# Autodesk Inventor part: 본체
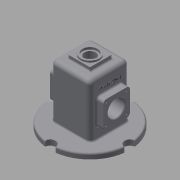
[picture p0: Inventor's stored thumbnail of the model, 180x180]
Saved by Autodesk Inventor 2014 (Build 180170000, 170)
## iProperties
Created: 2018-07
Part Number: 본체
Material: Generic
Document SubType Name: Modeling
Designer: kh
Density: 1 g/cm^3
Appearance: Default
Author: kh
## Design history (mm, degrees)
sketch "Sketch1"
  geometry: C1 r 75 at (0, 0); 1 further point
  constraints: 1 centre point, 1 coincident
  dimensions: "d0" = 150 diameter of C1
extrude "Extrusion1" new body sketch "Sketch1" distance "d1" = 10; taper "d2" = 0 deg
sketch "Sketch2"
  geometry: L1 (-37, -37)-(37, -37); L2 (37, -37)-(37, 37); L3 (37, 37)-(-37, 37); L4 (-37, 37)-(-37, -37); L5 (-37, -37)-(37, 37); L6 (37, -37)-(-37, 37); 1 further point
  constraints: 12 end point, 2 midpoint, 2 parallel, 1 horizontal, 1 perpendicular
  dimensions: "d3" = 74 distance of L2.end L3.end; "d4" = 74 distance of L1.end L2.end
extrude "Extrusion2" join sketch "Sketch2" distance "d5" = 100; taper "d6" = 0 deg
sketch "Sketch3"
  geometry: L1 (0, 74)-(0, 0) reference; L2 (0, 74)-(-100, 74) reference; L3 (-100, 0)-(-100, 74) reference; L4 (0, 0)-(-100, 0) reference; L5 (-20, 12)-(-70, 12); L6 (-70, 12)-(-70, 62); L7 (-70, 62)-(-20, 62); L8 (-20, 62)-(-20, 12); L9 (-20, 12)-(-70, 62); L10 (-70, 12)-(-20, 62); L11 (10, -38)-(10, 112) reference; L12 (10, 37)-(-46.721, 37); 2 further points
  constraints: 14 end point, 3 midpoint, 2 parallel, 2 perpendicular, 1 horizontal, 1 point on line
  dimensions: "d7" = 50 distance of L5.end L6.end; "d8" = 50 distance of L5.start L5.end; "d9" = 55 distance from line of L11 point (-45, 37)
extrude "Extrusion3" join sketch "Sketch3" distance "d10" = 13; taper "d11" = 0 deg
mirror "Mirror1"
sketch "Sketch4"
  geometry: L1 (0, 0)-(0, 109.307); L2 (0, 105)-(-32, 105); L3 (-37, 80)-(-50, 80) reference; L4 (-37, 10)-(-37, 110) reference; L5 (-75, 0)-(75, 0) reference; L6 (-32, 105)-(-32, 80); L7 (-32, 80)-(-25, 77.452); L8 (-25, 77.452)-(-25, 32.548); L9 (-37, 30)-(-50, 30) reference; L10 (-25, 32.548)-(-32, 30); L11 (-32, 30)-(-32, 0); L12 (-37, 110)-(37, 110) reference; L13 (-25, 55)-(-41.925, 55); L14 (32, 30)-(32, 0); L15 (25, 32.548)-(32, 30); L16 (25, 77.452)-(25, 32.548); L17 (32, 80)-(25, 77.452); L18 (32, 105)-(32, 80); L19 (0, 105)-(32, 105); L20 (32, 0)-(-32, 0)
  constraints: 30 end point, 6 symmetric about line, 3 perpendicular, 3 point on line, 2 parallel, 1 collinear, 1 midpoint, 1 vertical, 1 other
  dimensions: "d13" = 5 distance between parallel lines of L2 L12; "d14" = 32 distance of L2.start L2.end; "d16" = 32 distance between parallel lines of L1 L11; "d17" = 7 distance between parallel lines of L8 L6; "d18" = 50 distance of L10.end L6.end; "d19" = 110 deg angle of L11 L10
extrude "Extrusion4" cut sketch "Sketch4" stored distance "d20" = 64; taper "d21" = 0 deg
sketch "Sketch5"
  geometry: L1 (-70, 12)-(-20, 12) reference; L2 (-20, 12)-(-20, 62) reference; L3 (-20, 62)-(-70, 62) reference; L4 (-70, 62)-(-70, 12) reference; L5 (-20, 12)-(-70, 62); C1 r 16 at (-45, 37); 1 further point
  constraints: 2 end point, 1 centre point, 1 midpoint
  dimensions: "d22" = 32 diameter of C1
extrude "Extrusion5" cut sketch "Sketch5" stored distance "d23" = 64; taper "d24" = 0 deg
sketch "Sketch6"
  geometry: L1 (-37, -37)-(37, -37) reference; L2 (37, -37)-(37, 37) reference; L3 (37, 37)-(-37, 37) reference; L4 (-37, 37)-(-37, -37) reference; L5 (-20, -20)-(20, -20); L6 (20, -20)-(20, 20); L7 (20, 20)-(-20, 20); L8 (-20, 20)-(-20, -20); L9 (-20, -20)-(20, 20); L10 (20, -20)-(-20, 20); 1 further point
  constraints: 12 end point, 2 midpoint, 2 parallel, 1 horizontal, 1 perpendicular
  dimensions: "d25" = 40 distance of L6.end L7.end; "d26" = 40 distance of L5.end L6.end
extrude "Extrusion6" join sketch "Sketch6" distance "d27" = 7; taper "d28" = 0 deg
sketch "Sketch7"
  geometry: C1 r 17.5 at (0, 0); 1 further point
  constraints: 1 centre point, 1 coincident
  dimensions: "d29" = 35 diameter of C1
extrude "Extrusion7" join sketch "Sketch7" distance "d30" = 3; taper "d31" = 0 deg
hole "Hole1" diameter "d34" = 21; stored, may be unused: countersink angle "d38" = 90 deg, drill point angle "d40" = 118 deg; dims "d32" = 10, "d33" = 10, "d35" = 6, "d36" = 28, "d37" = 4, "d39" = 8
fillet "Fillet1" dims "d41" = 8
fillet "Fillet2" dims "d42" = 6
fillet "Fillet3" dims "d43" = 3
fillet "Fillet4" dims "d44" = 3
fillet "Fillet5" dims "d45" = 3
fillet "Fillet6" dims "d46" = 3
chamfer "Chamfer1" distance "d47" = 1; stored, may be unused: second distance "d48" = 2, angle "d49" = 45 deg
sketch "Sketch8"
  geometry: L1 (-70, 56)-(-70, 18) reference; L2 (-64, 12)-(-26, 12) reference; L3 (-20, 18)-(-20, 56) reference; L4 (-26, 62)-(-64, 62) reference; C1 r 17 at (-45, 37) reference; A1 r 6 centre (-64, 56) between (-64, 62) and (-70, 56) reference; A2 r 6 centre (-64, 18) between (-70, 18) and (-64, 12) reference; A3 r 6 centre (-26, 18) between (-26, 12) and (-20, 18) reference; A4 r 6 centre (-26, 56) between (-20, 56) and (-26, 62) reference; 1 further point
hole "Hole2" sketch "Sketch8" at (-64, 56), (-64, 18), (-26, 18), (-26, 56) diameter "d50" = 3.242; stored, may be unused: countersink angle "d54" = 90 deg, drill point angle "d56" = 118 deg; dims "d51" = 8, "d52" = 28, "d53" = 4, "d55" = 10
mirror "Mirror2"
fillet "Fillet7" dims "d57" = 8
sketch "Sketch9"
  geometry: L1 (0, 66)-(-89, 66) reference; L2 (-107, 46.5)-(-107, 11.5) reference; L3 (-80.002, 8.261)-(-80.002, 49.739); L4 (-80.002, 49.739)-(-73.998, 49.739); L5 (-73.998, 49.739)-(-73.998, 8.261); L6 (-73.998, 8.261)-(-80.002, 8.261); L7 (-77, 8.261)-(-77, 49.739); L8 (-80.002, 29)-(-73.998, 29); 2 further points
  constraints: 5 midpoint, 4 end point, 2 other
  dimensions: "d58" = 30 distance from line of point (-77, 29) L2; "d59" = 37 distance from line of point (-77, 29) L1
emboss "Emboss1" sketch "Sketch9" dims "d7" = 50, "d8" = 50, "d9" = 55, "d60" = 0.5, "d61" = 0
sketch "Sketch10"
  geometry: L1 (0, 0)-(0, 75); C1 r 10 at (0, 75); 1 further point
  constraints: 2 end point, 1 centre point, 1 coincident, 1 vertical, 1 vertical alignment, 1 other
  dimensions: "d62" = 20 diameter of C1
extrude "Extrusion8" cut sketch "Sketch10" stored distance "d63" = 3; taper "d64" = 0 deg
pattern_circular "Circular Pattern1" dims angle "d66" = 360 deg
body "Solid1"
node "Projected Loop1"
node "Projected Loop2"
node "Projected Loop3"
node "Projected Loop4"
